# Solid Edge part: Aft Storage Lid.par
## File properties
Author: m_hel
Template: Iso Metric Part.par
Last saved by: m_hel
Revision: 14
Application: Solid Edge
Accuracy: 0,990
Username: m_hel
Material: Textured White
Face Style: White painted
Fill Style: ANSI36(Marble)
Virtual Style: ANSI36(Marble)
Grouping: Uncategorized
LibraryName: Custom Materials
Coef. of Thermal Exp: 0.0
Thermal Conductivity: 0.0
Specific Heat: 0.0
Modulus of Elasticity: 0.0
Poisson's Ratio: 0.0
Yield Stress: 0.0
Ultimate Stress: 0.0
Elongation: 0.0
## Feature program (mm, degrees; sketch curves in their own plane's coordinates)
sketch for "unnamed Protrusion 1" plane through (0, 0, 0) normal (0, 0, 1) x-axis (1, 0, 0)
  line (-500, -225) -> (500, -225)
  line (500, -225) -> (500, 225)
  line (500, 225) -> (-500, 225)
  line (-500, 225) -> (-500, -225)
extrude "unnamed Protrusion 1" add finite 50 along -normal
fillet "Round_1" radius 20
fillet "Round_2" radius 20
thinwall "Thinwall_1"  Thickness = 10 mm
sketch for "unnamed Cutout 1" plane through (0, 0, 0) normal (0, 0, 1) x-axis (1, 0, 0)
  circle centre (0, -125) radius 35
extrude "unnamed Cutout 1" cut through along -normal
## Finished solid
Body 1: solid body, 36 faces, 74 edges, 40 vertices.
  Faces by surface: cylinder 17, plane 11, sphere 8
  Edges by curve: line 40, circle 34
Bounding box of the edges (mm; curved faces can reach further): 1000.000 x 450.000 x 50.000, from (-500, -225, -50) to (500, 225, 0).
Cylindrical faces by radius (mm): R10 x8, R20 x8, R35 x1
Spherical faces by radius (mm): R10 x4, R20 x4
Planar faces by outward normal: +x 2, +y 2, +z 1, -x 2, -y 2, -z 2
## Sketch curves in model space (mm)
circle centre (0, -125, 0) radius 35
line (500, -225, 0) -> (500, 225, 0)
line (500, 225, 0) -> (-500, 225, 0)
line (-500, 225, 0) -> (-500, -225, 0)
line (-500, -225, 0) -> (500, -225, 0)
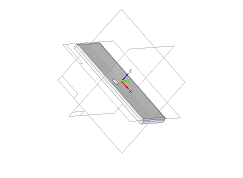
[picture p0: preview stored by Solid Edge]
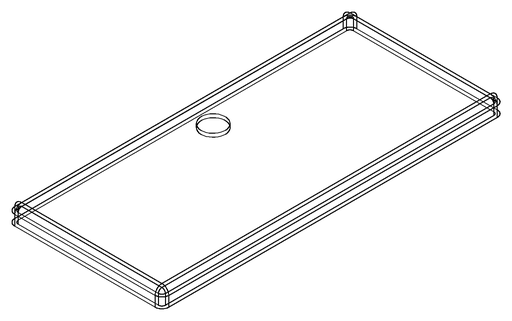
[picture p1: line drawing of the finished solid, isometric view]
